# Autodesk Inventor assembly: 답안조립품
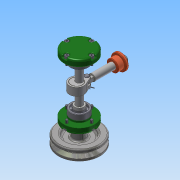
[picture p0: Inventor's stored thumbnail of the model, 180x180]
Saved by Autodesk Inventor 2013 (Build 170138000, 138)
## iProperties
Created: 2016-02
Part Number: 답안조립품
Document SubType Name: Assembly
Designer: Administrator
Author: Administrator
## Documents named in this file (16)
- C:\Users\Administrator\Desktop\460212V1008\답안조립품.iam
- C:\Users\Administrator\Desktop\460212V1008\본체.ipt
- C:\Users\Administrator\Desktop\460212V1008\V벨트풀리.ipt
- C:\Users\Administrator\Desktop\460212V1008\고정핀 1.2 x 10.ipt
- C:\Users\Administrator\Desktop\460212V1008\뒤커버.ipt
- C:\Users\Administrator\Desktop\460212V1008\링크.ipt
- C:\Users\Administrator\Desktop\460212V1008\멈춤나사 M3x8.ipt
- C:\Users\Administrator\Desktop\460212V1008\베어링 12 x 32 x 10.ipt
- C:\Users\Administrator\Desktop\460212V1008\볼트 M4 x 12.ipt
- C:\Users\Administrator\Desktop\460212V1008\부시.ipt
- C:\Users\Administrator\Desktop\460212V1008\슬라이드.ipt
- C:\Users\Administrator\Desktop\460212V1008\앞커버.ipt
- C:\Users\Administrator\Desktop\460212V1008\오일실 12 25 7.ipt
- C:\Users\Administrator\Desktop\460212V1008\키 4 x 4 x 10.ipt
- C:\Users\Administrator\Desktop\460212V1008\편심축.ipt
- C:\Users\Administrator\Desktop\460212V1008\핀 5 x 18.ipt
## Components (11 placed, 4 different names)
1. V벨트풀리:1
2. 고정핀 1.2 x 10:1 — 각도:1, 각도:2
3. 핀 5 x 18:1
4. ISO 4762 M4 x 12:1
5. ISO 4762 M4 x 12:3
6. ISO 4762 M4 x 12:4
7. ISO 4762 M4 x 12:5
8. ISO 4762 M4 x 12:2
9. ISO 4762 M4 x 12:6
10. ISO 4762 M4 x 12:7
11. ISO 4762 M4 x 12:8
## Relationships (2: Angle 2)
- 각도:1 [Angle]: 고정핀 1.2 x 10:1
- 각도:2 [Angle]: 고정핀 1.2 x 10:1
